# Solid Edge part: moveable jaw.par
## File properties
Title: Moveable Jaw
Author: Robert a Rhodes jr
Template: Normal.par
Last saved by: CADCIM
Revision: 10
Application: Solid Edge
Material: iron
Accuracy: 0.99
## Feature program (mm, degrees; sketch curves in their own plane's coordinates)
sketch for "unnamed Protrusion 1" plane through (0, 0, 0) normal (0, -1, 0) x-axis (1, 0, 0)
  line (-36.5256, 25.2528) -> (-36.5256, -34.7472)
  line (-36.5256, -34.7472) -> (-33.0256, -34.7472)
  line (-33.0256, -34.7472) -> (-33.0256, -32.2472)
  line (-33.0256, -32.2472) -> (-30.5256, -32.2472)
  line (-30.5256, -32.2472) -> (-30.5256, -29.7472)
  line (-30.5256, -29.7472) -> (-28.0256, -29.7472)
  line (-28.0256, -29.7472) -> (-28.0256, -27.2472)
  line (-28.0256, -27.2472) -> (-25.5256, -27.2472)
  line (-25.5256, -27.2472) -> (-25.5256, -24.7472)
  line (-25.5256, -24.7472) -> (-23.0256, -24.7472)
  line (-23.0256, -24.7472) -> (-23.0256, -22.2472)
  line (-23.0256, -22.2472) -> (-20.5256, -22.2472)
  line (-20.5256, -22.2472) -> (-20.5256, -19.7472)
  line (-20.5256, -19.7472) -> (-18.0256, -19.7472)
  line (-18.0256, -22.2472) -> (-18.0256, -19.7472)
  line (-15.5256, -22.2472) -> (-18.0256, -22.2472)
  line (-15.5256, -24.7472) -> (-15.5256, -22.2472)
  line (-13.0256, -24.7472) -> (-15.5256, -24.7472)
  line (-13.0256, -27.2472) -> (-13.0256, -24.7472)
  line (-10.5256, -27.2472) -> (-13.0256, -27.2472)
  line (-10.5256, -29.7472) -> (-10.5256, -27.2472)
  line (-8.0256, -29.7472) -> (-10.5256, -29.7472)
  line (-8.0256, -32.2472) -> (-8.0256, -29.7472)
  line (-5.5256, -32.2472) -> (-8.0256, -32.2472)
  line (-5.5256, -34.7472) -> (-5.5256, -32.2472)
  line (-2.0256, -34.7472) -> (-5.5256, -34.7472)
  line (-2.0256, -34.7472) -> (-2.0256, 25.2528)
  line (-2.0256, 25.2528) -> (-36.5256, 25.2528)
extrude "unnamed Protrusion 1" add finite 18 along -normal
sketch for "Hole_1" plane through (-19.2756, 9, 25.2528) normal (0, 0, 1) x-axis (1, 0, 0)
  hole centre (0, 0) bore radius 6
hole "Hole_1" diameter 12 finite  VBottomAngle = 118 deg
sketch for "Hole_2" plane through (-2.0256, 9, -4.7472) normal (1, 0, 0) x-axis (0, 1, 0)
  hole centre (0, 23) bore radius 4.5
hole "Hole_2" diameter 9 through
chamfer "Chamfer_1" setback 2
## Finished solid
Body 1: solid body, 38 faces, 98 edges, 60 vertices.
  Faces by surface: plane 34, cylinder 3, cone 1
  Edges by curve: line 92, circle 4, intersection 2
Bounding box of the edges (mm): 34.500 x 18.000 x 60.000, from (-36.5256, 0, -34.7472) to (-2.0256, 18, 25.2528).
Cylindrical faces by radius (mm): R4.5 x2, R6 x1
Conical faces (half-angle, radius in mm at the cone's reference point): 59 deg R6 x1
Planar faces by outward normal: +x 7, +y 1, +z 1, -x 7, -y 1, -z 13, oblique 4
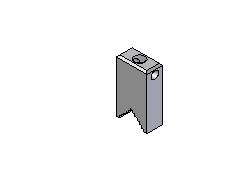
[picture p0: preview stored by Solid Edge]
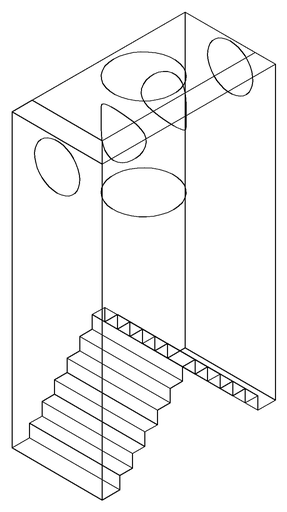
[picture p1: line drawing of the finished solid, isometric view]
